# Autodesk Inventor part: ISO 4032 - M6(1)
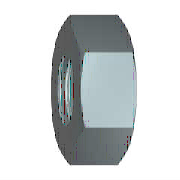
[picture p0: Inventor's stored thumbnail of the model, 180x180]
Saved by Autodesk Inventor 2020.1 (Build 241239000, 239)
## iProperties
Created: 2019-01
Part Number: ISO 4032 - M6(1)
Material: Edelstahl, 440C
Description: Sechskantmutter
Document SubType Name: Modeling
Standard: ISO 4032
Designer: lutzd
Standards Organization: DIN
Language: de-DE
Size Designation: M6
Categories: <MemberInstance><Categories><Category DisplayName="Verbindungselemente" InternalName="e4da775c-781d-43d5-af7c-5136215cf5a6" Mnemonic="FSTN"><Category DisplayNam
Mass: 2.60564 g
Surface Area: 3.63838 cm^2
Volume: 0.336211 cm^3
Density: 7.75 g/cm^3
Appearance: Halbpoliert
IsCustomPart: 0
Author: lutzd
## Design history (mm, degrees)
workaxis "Work Axis1"
workplane "Work Plane1"
sketch "Skizze1"
  geometry: L1 (-5.774, 0)-(-2.887, 5); L2 (-2.887, 5)-(2.887, 5); L3 (2.887, 5)-(5.774, 0); L4 (5.774, 0)-(2.887, -5); L5 (2.887, -5)-(-2.887, -5); L6 (-2.887, -5)-(-5.774, 0); 2 further points
  constraints: 12 end point, 1 coincident, 1 horizontal, 11 other
  dimensions: "d0" = 11.54701 distance of L3.end L1.start (= 1.1547 x SW)
extrude "Körper" new body sketch "Skizze1" distance "d1" = 5.2 (= KOH); taper "d2" = 0 deg
sketch "Skizze2"
  geometry: L1 (0, 2.887)-(0, 5.774) reference; L2 (0, 5.774)-(5.2, 5.774) reference; L3 (5.2, 2.887)-(5.2, 5.774) reference; L4 (-1.04, 0)-(6.24, 0) reference; L5 (0.764, 5.774)-(0, 4.45); L6 (4.436, 5.774)-(5.2, 4.45)
  constraints: 4 end point, 4 point on line
  dimensions: "d3" = 30 deg angle of L1 L5 (= ANG1); "d4" = 30 deg angle of L3 L6 (= ANG2); "d5" = 8.9 diameter of L5.end L4 (= SW0); "d6" = 8.9 diameter of L6.end L4 (= SW01)
revolve "Fase1" stored, may be unused: angle "d7" = 90 deg
sketch "Skizze3"
  geometry: 4 further points
  constraints: 1 coincident, 1 other
hole "Gewinde" sketch "Skizze3" diameter "d25" = 4.917; stored, may be unused: countersink angle "d29" = 82 deg, drill point angle "d31" = 118 deg; dims "d26" = 6, "d27" = 4, "d28" = 2, "d30" = 8
body "Solid1"
chamfer "Fase2" distance "d8" = 0.54127 (= -0.5 x GD1 + 0.5 x NND); stored, may be unused: angle "d9" = 30 deg, second distance "d40" = 0.54127 (= -0.5 x GD1 + 0.5 x NND)
chamfer "Fase3" distance "d10" = 0.54127 (= -0.5 x GD1 + 0.5 x NND); stored, may be unused: angle "d11" = 30 deg, second distance "d41" = 0.54127 (= -0.5 x GD1 + 0.5 x NND)
other parameters: "ANG1" = 30 deg [user parameter; used in 1 equation term], "ANG2" = 30 deg [user parameter; used in 1 equation term], "NND" = 6 [user parameter; used in 4 equation terms], "KOH" = 5.2 [user parameter; used in 1 equation term], "SW0" = 8.9 [user parameter; used in 1 equation term], "SW01" = 8.9 [user parameter; used in 1 equation term], "GD1" = 4.91747 (computed from THREADDIA, PTC, TOA) [user parameter; used in 4 equation terms], "d13" = 0, "d14" = 0, "d39" = 0, "d42" = 0, "GUL" = 0.54127 (= 0.541266 x PTC) [user parameter], "THREADDIA" = 6 [user parameter; used in 1 equation term], "TOA" = 30 deg [user parameter; used in 1 equation term], "PTC" = 1 [user parameter; used in 4 equation terms], "E0" = 11.55 (= 1.155 x SW) [user parameter], "GAL" = 0.54127 (= 0.541266 x PTC) [user parameter]
